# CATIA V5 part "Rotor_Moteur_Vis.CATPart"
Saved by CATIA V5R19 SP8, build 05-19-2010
Part number: Rotor_Moteur_Vis
Nomenclature: 70_e
Bounding box of the stored display mesh (mm): x -16.996 to 16.996, y -16.996 to 16.996, z 16 to 93
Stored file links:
  C:\Users\rphgr\Desktop\0_Tapis_TC520B_vitesse\Rotor_Moteur_Vis.CATPart
  D:\Documents\1_Travail\1 - ac-limoges.fr\ac-limoges.fr\Emmanuel Maynard - STI2D_Turgot\3 - Supports\Tapis de course TC520B\Tapis de course TC520B_Ca\Roue_1.CATPart
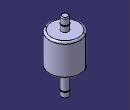
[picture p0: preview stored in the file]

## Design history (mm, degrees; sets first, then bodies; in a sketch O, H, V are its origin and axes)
Parameters
  LargeurDenture = 16 mm
  AlphaCopie = 60 deg
  Integer = 6
  Integer = -1
  DiamPrimitif = 5.9582 mm
  ANGLE = 25 deg
  Phin = 8.0728 deg
  Dn = 7.3082 mm
  Phim = 2.7929 deg
  Dm = 6.4082 mm
  Phil = 0.5585 deg
  Dl = 5.8684 mm
  PhiSymetrie = 15 deg
  Phik = 0.109 deg
  Dk = 5.6887 mm
  Phij = 5.2557 deg
  Dj = 6.8582 mm
  Phii = 0.3061 deg
  Di = 5.7786 mm
  AlphaSymetrieCopie = 30 deg
  CongePied = 0.342 mm
  PhiTete = 11.1513 deg
  PhiPrimitif = 0.854 deg
  DiamTete = 7.7582 mm
  DiamPied = 3.7082 mm
  DiamBase = 5.5989 mm
  LargeurDenture.1 = 16 mm
  AlphaCopie.1 = 60 deg
  Integer = 6
  Integer = -1
  DiamPrimitif.1 = 5.9582 mm
  ANGLE = 25 deg
  Phin.1 = 8.0728 deg
  Dn.1 = 7.3082 mm
  Phim.1 = 2.7929 deg
  Dm.1 = 6.4082 mm
  Phil.1 = 0.5585 deg
  Dl.1 = 5.8684 mm
  PhiSymetrie.1 = 15 deg
  Phik.1 = 0.109 deg
  Dk.1 = 5.6887 mm
  Phij.1 = 5.2557 deg
  Dj.1 = 6.8582 mm
  Phii.1 = 0.3061 deg
  Di.1 = 5.7786 mm
  AlphaSymetrieCopie.1 = 30 deg
  CongePied.1 = 0.342 mm
  PhiTete.1 = 11.1513 deg
  PhiPrimitif.1 = 0.854 deg
  DiamTete.1 = 7.7582 mm
  DiamPied.1 = 3.7082 mm
  DiamBase.1 = 5.5989 mm
AxisSystem1: origin (0, 0, 0), X (1, 0, 0), Y (0, 1, 0), Z (0, 0, 1)
Body1 (main body)
  Sketch1 on YZ plane of AxisSystem1, origin (0, 0, 0), H (0, 1, 0), V (0, 0, 1)
    point P1 (0, 0)
    line L1 (-4, 16) -> (-4, 43)
    line L2 (-4, 43) -> (-17, 43)
    line L3 (-17, 43) -> (-17, 79)
    line L4 (-17, 79) -> (-4, 79)
    line L5 (-4, 79) -> (-4, 93)
    line L6 (-4, 93) -> (0, 93)
    axis line L7 (0, 0) -> (0, 102.2481)
    line L8 (-4, 16) -> (0, 16)
    point P10 (0, 16)
    reference intersected line E1 through (0, 0) direction (-1, 0) from XY plane of AxisSystem1
    reference intersected line E2 through (0, 0) direction (-1, 0) from XY plane of AxisSystem1
    distance L2 L4 = 36
    distance L7 L5 = 4
    distance L3 L7 = 17
    distance L1 L7 = 4
    distance L8 H = 16
    distance L2 E1 = 43
    distance L6 E2 = 93
    vertical: L7 V
    coincidence: P10 L7
    horizontal: L8 H
  Shaft1: profile Sketch1, axis Sketch1.L7, angle 360
  Fillet1: radius 2, on face of Shaft1 from Sketch1.L3
  Sketch2 on YZ plane of AxisSystem1, origin (0, 0, 0), H (0, 1, 0), V (0, 0, 1)
    line L1 (-11.1014, 22) -> (-3.5, 22)
    line L2 (-3.5, 22) -> (-3.5, 21)
    line L3 (-3.5, 21) -> (-11.1014, 21)
    line L4 (-11.1014, 21) -> (-11.1014, 22)
    point P5 (-11.1014, 86)
    line L5 (-11.1014, 86) -> (-3.5, 86)
    line L6 (-3.5, 86) -> (-3.5, 85)
    line L7 (-3.5, 85) -> (-11.1014, 85)
    line L8 (-11.1014, 85) -> (-11.1014, 86)
    point P7 (-3.5, 85)
    reference projected line E1 through (0, 0) direction (0, 1) from axis of face of Shaft1 from Sketch1.L1
    reference intersected line E2 (-4, 93) -> (4, 93) from face of Shaft1 from Sketch1.L6
    distance L3 L1 = 1
    distance L2 E1 = 3.5
    distance L7 L5 = 1
    distance L5 E2 = 7
    distance L3 H = 21
    horizontal: L1 H, L3 H, L5 H, L7 H
    vertical: L2 V, L4 V, L6 V, L8 V
    coincidence: P5 L4, P7 L2
  Groove1: profile Sketch2, axis axis of face of Shaft1 from Sketch1.L3, angle 360
  Chamfer1: length 1, angle 45, on face of Shaft1 from Sketch1.L6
